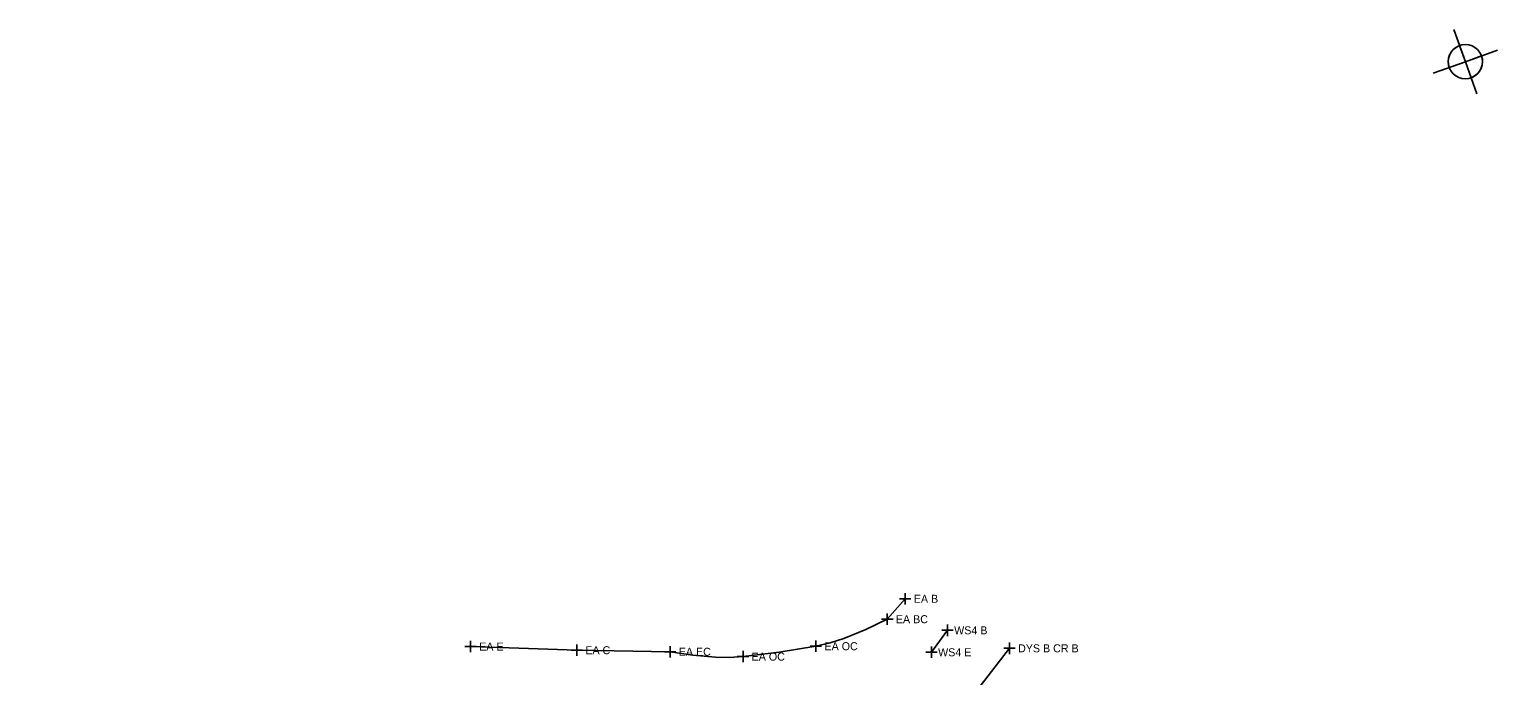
# Model space of a CAD drawing. Extents: x 1324236 to 1326110, y 459090 to 460782.
# Drawn here: x 1325315.8 to 1325572.7, y 460526.7 to 460639.8 of the extents above; entities that cross this region are included whole.
import ezdxf

# ---------------------------------------------------------------- set-up
doc = ezdxf.new("R2010")
doc.units = 0
for name, color, linetype in [('BD_X_Canopy', 7, 'Continuous'), ('DR_X_Ditch', 7, 'Continuous'), ('DR_X_Storm_Sewer', 7, 'Continuous'), ('DT_X_Island', 7, 'Continuous'), ('DV_X_Property_Line', 7, 'Continuous'), ('GT_Project_Soil_Boring', 7, 'Continuous'), ('LT_X_Poles', 7, 'Continuous'), ('PM_X_Edge_Line', 7, 'Continuous'), ('RW_X_CL', 7, 'Continuous')]:
    doc.layers.add(name, color=color, linetype=linetype)

msp = doc.modelspace()

# ---------------------------------------------------------------- linework, layer by layer
at = {"layer": 'BD_X_Canopy'}
msp.add_lwpolyline([(1325487.31, 460531.49), (1325482.01, 460524.62), (1325468.2, 460505.38), (1325449.72, 460480.14), (1325435.41, 460460.81), (1325430.06, 460453.47), (1325411.08, 460426.97), (1325392.29, 460401.31), (1325374.47, 460377.45), (1325359.08, 460355.34), (1325347.31, 460339.76), (1325334.63, 460323.86), (1325318.91, 460302.58), (1325303.42, 460281.57), (1325299.27, 460276.07), (1325289.28, 460262.48), (1325282.05, 460252.54), (1325264.96, 460229.27), (1325246.47, 460204.3), (1325228.59, 460180.03), (1325210.75, 460156.01)], dxfattribs=at)
at = {"layer": 'DR_X_Ditch'}
msp.add_lwpolyline([(1325469.07, 460540.15), (1325465.93, 460536.58), (1325462.18, 460534.79), (1325458.33, 460533.22), (1325458.33, 460533.22), (1325455.92, 460532.43), (1325453.44, 460531.86), (1325453.44, 460531.86), (1325447, 460530.82), (1325447, 460530.82), (1325440.69, 460530.04), (1325440.69, 460530.04), (1325438.27, 460529.89), (1325435.85, 460529.95), (1325435.85, 460529.95), (1325431.89, 460530.32), (1325427.94, 460530.89), (1325427.94, 460530.89), (1325411.59, 460531.16), (1325393.02, 460531.8)], dxfattribs=at)
at = {"layer": 'DR_X_Storm_Sewer'}
msp.add_line((1325487.31, 460531.49), (1325482.01, 460524.62), dxfattribs=at)
at = {"layer": 'DT_X_Island'}
msp.add_line((1325487.31, 460531.49), (1325482.01, 460524.62), dxfattribs=at)
at = {"layer": 'DV_X_Property_Line'}
for p, q in [((1325469.07, 460539.15), (1325469.07, 460541.15)), ((1325468.07, 460540.15), (1325470.07, 460540.15)), ((1325464.93, 460536.58), (1325466.93, 460536.58)), ((1325465.93, 460535.58), (1325465.93, 460537.58)), ((1325392.02, 460531.8), (1325394.02, 460531.8)), ((1325393.02, 460530.8), (1325393.02, 460532.8)), ((1325410.59, 460531.16), (1325412.59, 460531.16)), ((1325411.59, 460530.16), (1325411.59, 460532.16)), ((1325426.94, 460530.89), (1325428.94, 460530.89)), ((1325427.94, 460529.89), (1325427.94, 460531.89)), ((1325440.69, 460529.04), (1325440.69, 460531.04)), ((1325452.44, 460531.86), (1325454.44, 460531.86)), ((1325453.44, 460530.86), (1325453.44, 460532.86)), ((1325439.69, 460530.04), (1325441.69, 460530.04))]:
    msp.add_line(p, q, dxfattribs=at)
at = {"layer": 'GT_Project_Soil_Boring'}
for p, q in [((1325567.08, 460634.12), (1325565.05, 460639.77)), ((1325566.07, 460636.95), (1325567.08, 460634.12)), ((1325567.08, 460634.12), (1325572.73, 460636.15)), ((1325567.08, 460634.12), (1325561.43, 460632.1)), ((1325567.08, 460634.12), (1325564.26, 460633.11)), ((1325567.08, 460634.12), (1325569.9, 460635.14)), ((1325567.08, 460634.12), (1325569.11, 460628.47)), ((1325568.09, 460631.3), (1325567.08, 460634.12))]:
    msp.add_line(p, q, dxfattribs=at)
msp.add_circle((1325567.08, 460634.12), 3, dxfattribs=at)
for start, end in [(109.7344, 199.7344), (289.7344, 19.7344)]:
    msp.add_arc((1325567.08, 460634.12), 3, start, end, dxfattribs=at)
at = {"layer": 'LT_X_Poles'}
for p, q in [((1325476.47, 460534.64), (1325473.65, 460530.8)), ((1325487.31, 460531.49), (1325482.01, 460524.62))]:
    msp.add_line(p, q, dxfattribs=at)
at = {"layer": 'PM_X_Edge_Line'}
msp.add_line((1325476.47, 460534.64), (1325473.65, 460530.8), dxfattribs=at)
at = {"layer": 'RW_X_CL'}
for p, q in [((1325475.47, 460534.64), (1325477.47, 460534.64)), ((1325476.47, 460533.64), (1325476.47, 460535.64)), ((1325472.65, 460530.8), (1325474.65, 460530.8)), ((1325473.65, 460529.8), (1325473.65, 460531.8)), ((1325486.31, 460531.49), (1325488.31, 460531.49)), ((1325487.31, 460530.49), (1325487.31, 460532.49))]:
    msp.add_line(p, q, dxfattribs=at)

# ---------------------------------------------------------------- texts
at = {"layer": 'DV_X_Property_Line'}
for s, p in [('EA B', (1325470.57, 460539.45)), ('EA BC', (1325467.43, 460535.88)), ('EA E', (1325394.52, 460531.1)), ('EA C', (1325413.09, 460530.46)), ('EA EC', (1325429.44, 460530.19)), ('EA OC', (1325442.19, 460529.34)), ('EA OC', (1325454.94, 460531.16))]:
    msp.add_text(s, height=1.4, dxfattribs=at).set_placement(p)
at = {"layer": 'RW_X_CL'}
for s, p in [('WS4 B', (1325477.63, 460533.94)), ('WS4 E', (1325474.82, 460530.1)), ('DYS B CR B', (1325488.81, 460530.79))]:
    msp.add_text(s, height=1.4, dxfattribs=at).set_placement(p)

doc.saveas('drawing.dxf')
